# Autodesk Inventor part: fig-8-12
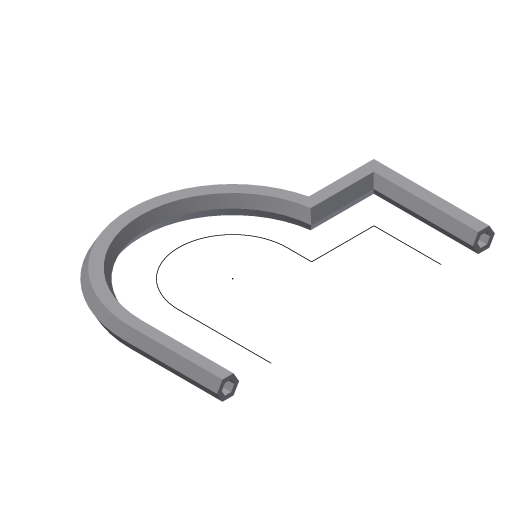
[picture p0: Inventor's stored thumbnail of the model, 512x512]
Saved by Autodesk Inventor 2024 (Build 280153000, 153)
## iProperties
Created: 2004-05
Part Number: fig-8-12
Document SubType Name: Modeling
Designer: CADCIM Technologies
Manufacturer: Standard
Standards Organization: Custom
Density: 1 g/cm^3
Material: Generic
Appearance: Default
Author: CADCIM Technologies
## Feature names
1. Sweep5
## Parameters: d4 = 0, d5 = 0
